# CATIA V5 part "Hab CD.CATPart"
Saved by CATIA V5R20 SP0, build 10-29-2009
Part number: Hab CD
Bounding box of the stored display mesh (mm): x -20 to -10, y 60.579 to 209.726, z -9.987 to 441.056
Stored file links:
  D:\Dropbox\IAO_2012\IAO_2012_766_vlaroche\vlaroche\vlaroche\IAO\A rendre\Hab CD.CATPart
  D:\Catia\IAO\A rendre\Assemblage.CATProduct
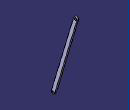
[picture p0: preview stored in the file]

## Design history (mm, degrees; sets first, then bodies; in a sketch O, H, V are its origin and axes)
Set1
  Point1: linked copy from another document
  Point2: linked copy from another document
Body1 (main body)
  Sketch1 on yz-plane, origin (0, 0, 0), H (0, 1, 0), V (0, 0, 1)
    construction line L1 (199.7278, 431.0686) -> (70.5772, 0)
    point P1 (199.7278, 431.0686)
    point P2 (70.5772, 0)
    line L2 (209.3071, 428.1986) -> (80.1565, -2.87)
    line L3 (60.9979, 2.87) -> (190.1485, 433.9386)
    arc A1 centre (70.5772, 0) radius 10 from (80.1565, -2.87) to (60.9979, 2.87) cw
    arc A2 centre (199.7278, 431.0686) radius 10 from (190.1485, 433.9386) to (209.3071, 428.1986) cw
    reference projected point E1 (199.7278, 431.0686) from Point1
    reference projected point E2 (70.5772, 0) from Point2
    circle A3 centre (70.5772, 0) radius 5
    point P7 (75.5772, 0)
    circle A4 centre (199.7278, 431.0686) radius 5
    distance L1 L2 = 10
    radius A3 = 5
    radius A4 = 5
    tangency: A1 L2, A2 L2, A1 L3, A2 L3
    coincidence: P1 E1, P2 E2, A3 P7, P7 H
  Pad1: profile Sketch1, direction (1, 0, 0), length -10, opposite side length 20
